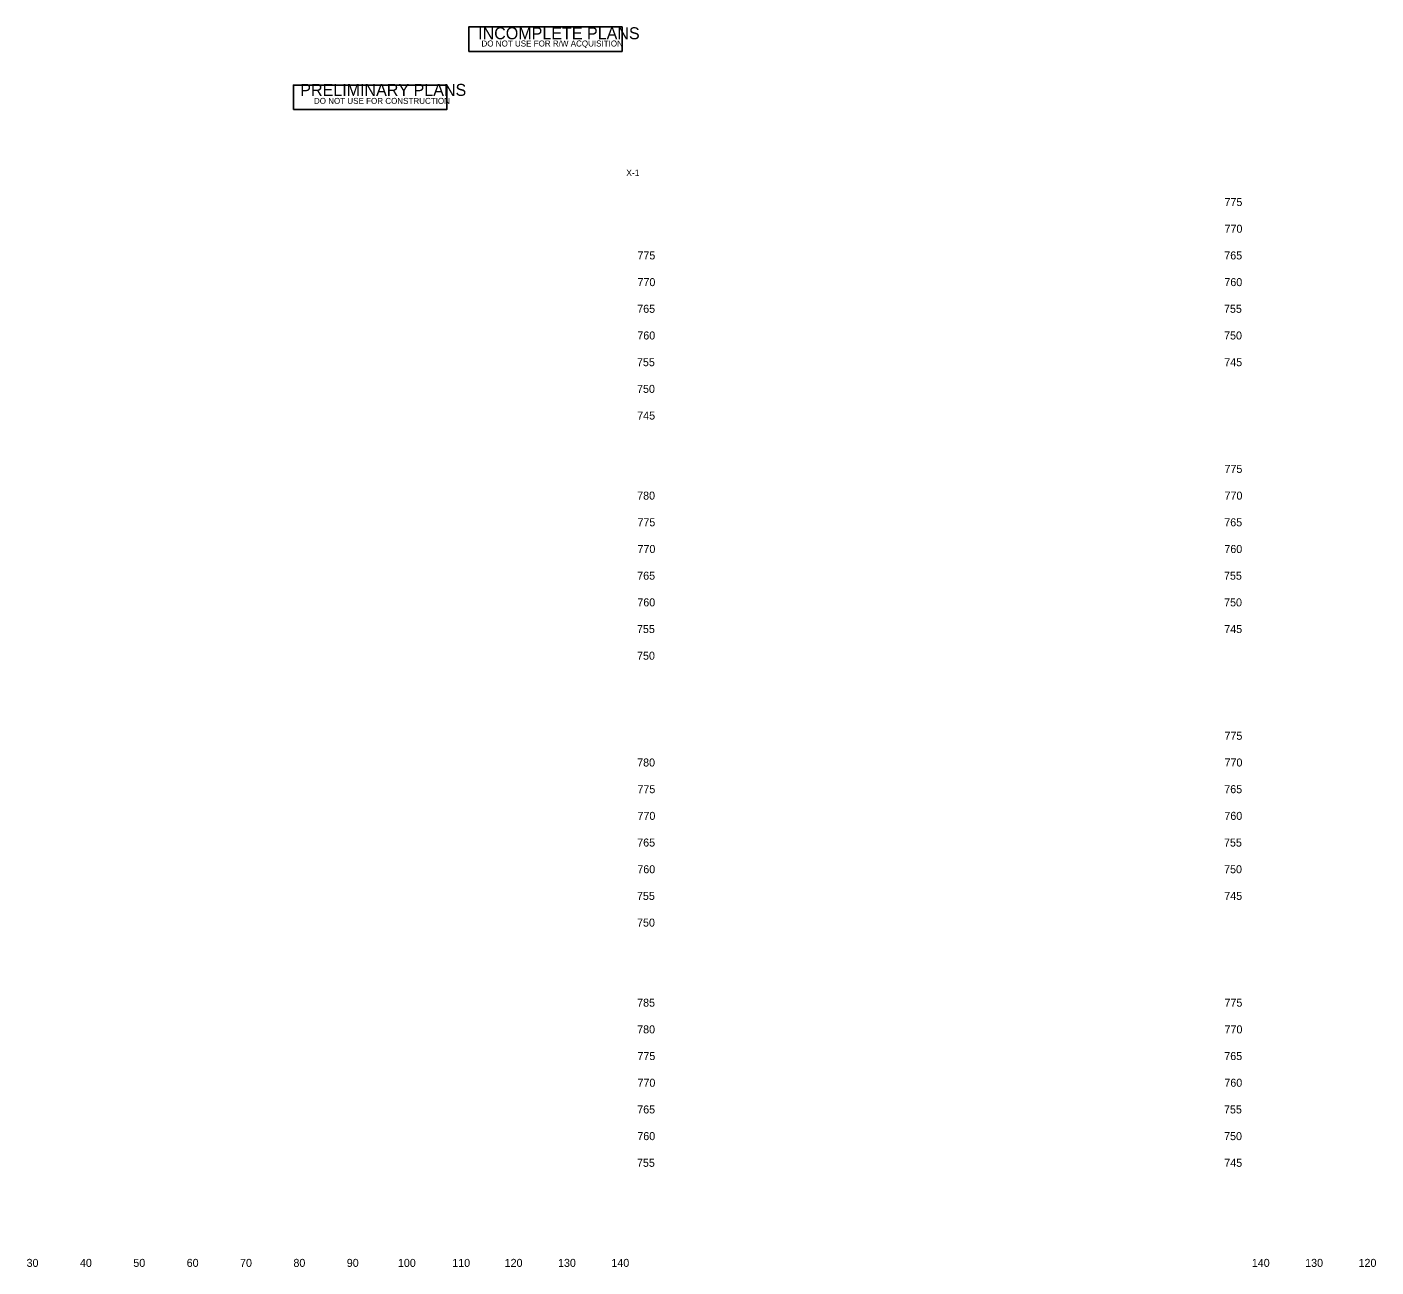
# Model space of a CAD drawing. Extents: x 2473106 to 2475402, y 633617 to 633851.
# Drawn here: x 2473684.6 to 2473937.4, y 633618.8 to 633851.1 of the extents above; entities that cross this region are included whole.
import ezdxf

# ---------------------------------------------------------------- set-up
doc = ezdxf.new("R2010")
doc.units = 0
for name, color, linetype in [('Exist Cross Section Cell', 7, 'Continuous'), ('Exist XS Ground Line', 7, 'Continuous'), ('Prop CMT Shld Paved Course 1', 7, 'Continuous'), ('Prop XS SE Text', 7, 'Continuous')]:
    doc.layers.add(name, color=color, linetype=linetype)

msp = doc.modelspace()

# ---------------------------------------------------------------- linework, layer by layer
at = {"layer": 'Prop CMT Shld Paved Course 1'}
for points in [[(2473767.41, 633846.53), (2473767.41, 633851.12), (2473796.12, 633851.12), (2473796.12, 633846.53)], [(2473734.56, 633835.67), (2473734.56, 633840.23), (2473763.28, 633840.2), (2473763.27, 633835.64)]]:
    msp.add_lwpolyline(points, close=True, dxfattribs=at)

# ---------------------------------------------------------------- texts
at = {"layer": 'Exist Cross Section Cell'}
for s, p in [('30', (2473684.55, 633618.82)), ('40', (2473694.55, 633618.82)), ('50', (2473704.55, 633618.82)), ('60', (2473714.55, 633618.82)), ('70', (2473724.55, 633618.82)), ('80', (2473734.55, 633618.82)), ('90', (2473744.55, 633618.82)), ('100', (2473754.13, 633618.82)), ('110', (2473764.31, 633618.82)), ('120', (2473774.13, 633618.82)), ('130', (2473784.13, 633618.82)), ('140', (2473794.13, 633618.82)), ('140', (2473914.13, 633618.82)), ('130', (2473924.13, 633618.82)), ('120', (2473934.13, 633618.82))]:
    msp.add_text(s, height=1.5, dxfattribs=at).set_placement(p)
at = {"layer": 'Exist XS Ground Line'}
for s, p in [('775', (2473909.01, 633817.57)), ('770', (2473909.02, 633812.57)), ('775', (2473799.01, 633807.57)), ('765', (2473908.97, 633807.57)), ('770', (2473799.02, 633802.57)), ('760', (2473908.99, 633802.57)), ('765', (2473798.97, 633797.57)), ('755', (2473908.92, 633797.57)), ('760', (2473798.99, 633792.57)), ('750', (2473908.94, 633792.57)), ('755', (2473798.92, 633787.57)), ('745', (2473908.97, 633787.57)), ('750', (2473798.94, 633782.57)), ('745', (2473798.97, 633777.57)), ('775', (2473909.01, 633767.57)), ('780', (2473798.96, 633762.57)), ('770', (2473909.02, 633762.57)), ('775', (2473799.01, 633757.57)), ('765', (2473908.97, 633757.57)), ('770', (2473799.02, 633752.57)), ('760', (2473908.99, 633752.57)), ('765', (2473798.97, 633747.57)), ('755', (2473908.92, 633747.57)), ('760', (2473798.99, 633742.57)), ('750', (2473908.94, 633742.57)), ('755', (2473798.92, 633737.57)), ('745', (2473908.97, 633737.57)), ('750', (2473798.94, 633732.57)), ('775', (2473909.01, 633717.57)), ('780', (2473798.96, 633712.57)), ('770', (2473909.02, 633712.57)), ('775', (2473799.01, 633707.57)), ('765', (2473908.97, 633707.57)), ('770', (2473799.02, 633702.57)), ('760', (2473908.99, 633702.57)), ('765', (2473798.97, 633697.57)), ('755', (2473908.92, 633697.57)), ('760', (2473798.99, 633692.57)), ('750', (2473908.94, 633692.57)), ('755', (2473798.92, 633687.57)), ('745', (2473908.97, 633687.57)), ('750', (2473798.94, 633682.57)), ('785', (2473798.95, 633667.57)), ('775', (2473909.01, 633667.57)), ('780', (2473798.96, 633662.57)), ('770', (2473909.02, 633662.57)), ('775', (2473799.01, 633657.57)), ('765', (2473908.97, 633657.57)), ('770', (2473799.02, 633652.57)), ('760', (2473908.99, 633652.57)), ('765', (2473798.97, 633647.57)), ('755', (2473908.92, 633647.57)), ('760', (2473798.99, 633642.57)), ('750', (2473908.94, 633642.57)), ('755', (2473798.92, 633637.57)), ('745', (2473908.97, 633637.57))]:
    msp.add_text(s, height=1.5, dxfattribs=at).set_placement(p)
at = {"layer": 'Prop CMT Shld Paved Course 1'}
for s, height, p in [('INCOMPLETE PLANS', 2.25, (2473769.16, 633848.82)), ('DO NOT USE FOR R/W ACQUISITION', 1.125, (2473769.79, 633847.46)), ('PRELIMINARY PLANS', 2.25, (2473735.83, 633838.21)), ('DO NOT USE FOR CONSTRUCTION', 1.125, (2473738.39, 633836.71))]:
    msp.add_text(s, height=height, dxfattribs=at).set_placement(p)
at = {"layer": 'Prop XS SE Text'}
msp.add_text('X-1', height=1.2, dxfattribs=at).set_placement((2473796.91, 633823.21))

doc.saveas('drawing.dxf')
